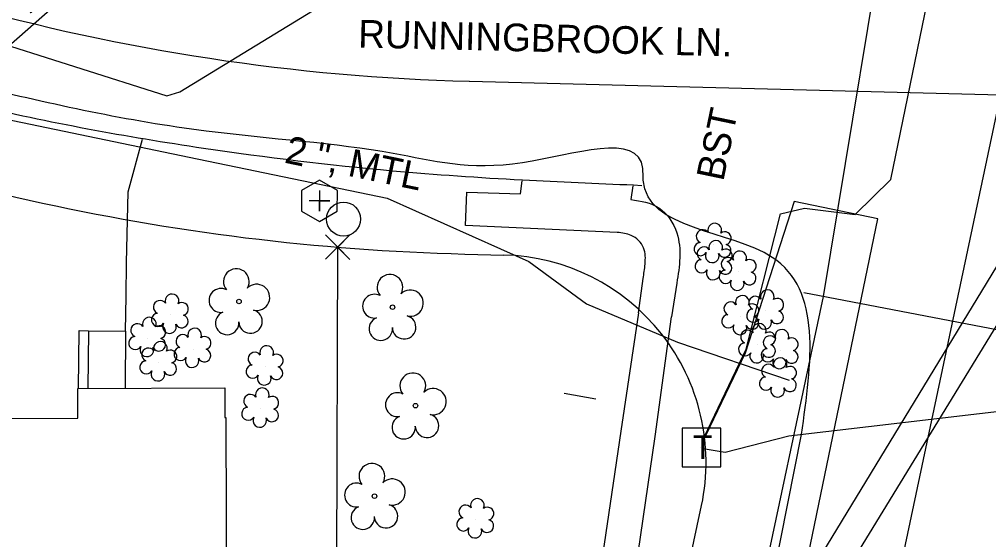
# Model space of a CAD drawing. Extents: x 1614427 to 1617186, y 896524 to 905462.
# Drawn here: x 1616487.6 to 1616627.8, y 901599.9 to 901675.1 of the extents above; entities that cross this region are included whole.
import ezdxf

# ---------------------------------------------------------------- set-up
doc = ezdxf.new("R2010")
doc.units = 0
for name, color, linetype in [('Exist Building', 7, 'Continuous'), ('Exist Horizontal Alignment', 7, 'Continuous'), ('Exist Other Culture Area Outline', 7, 'Continuous'), ('Exist Other Culture Sign', 7, 'Continuous'), ('Exist Property Corner CELL', 7, 'Continuous'), ('Exist Property Line', 7, 'Continuous'), ('Exist Right of Way Line', 7, 'Continuous'), ('Exist Roads Curbs', 7, 'Continuous'), ('Exist Roads EOP', 7, 'Continuous'), ('Exist Roads EOP Other', 7, 'Continuous'), ('Exist Roads EOP Text', 7, 'Continuous'), ('Exist Structure Minor Pipes RCP 18 Inch', 7, 'Continuous'), ('Exist Structure Minor Pipes RCP 18 Inch Text', 7, 'Continuous'), ('Exist Utilities Gas UG Line SUE LOS B', 7, 'Continuous'), ('Exist Utilities Gas UG Line SUE LOS B Text', 7, 'Continuous'), ('Exist Utilities Other Pole CELL', 7, 'Continuous'), ('Exist Utilities Sanitary Sewer Clean-Out CELL', 7, 'Continuous'), ('Exist Utilities Telephone Pedestal CELL', 7, 'Continuous'), ('Exist Utilities Telephone UG Cable SUE LOS B', 7, 'Continuous'), ('Exist Utilities Telephone UG FO SUE LOS D', 7, 'Continuous'), ('Exist Utilities TV UG FO Cable SUE LOS D', 7, 'Continuous'), ('Exist Utilities Water UG Line SUE LOS B', 7, 'Continuous'), ('Exist Vegetation Shrub CELL', 7, 'Continuous'), ('Exist Vegetation Tree CELL', 7, 'Continuous')]:
    doc.layers.add(name, color=color, linetype=linetype)

# ---------------------------------------------------------------- blocks, each defined once
blk = doc.blocks.new('EXIST UTILITIES SANITARY SEWER CLEAN-OUT')
at = {"layer": 'Exist Utilities Sanitary Sewer Clean-Out CELL'}
blk.add_line((0, 0), (0, 0), dxfattribs=at)
blk.add_lwpolyline([(-0.0516, 0.0299), (-0.0517, -0.0297), (-0.0001, -0.0596), (0.0516, -0.0299), (0.0517, 0.0297), (0.0001, 0.0596)], close=True, dxfattribs=at)
blk.add_lwpolyline([(0, 0.0302), (0, -0.0302), (0, 0), (0.0302, 0), (-0.0302, 0)], dxfattribs=at)
blk = doc.blocks.new('EXIST UTILITIES TELEPHONE PEDESTAL')
at = {"layer": 'Exist Utilities Telephone Pedestal CELL'}
blk.add_line((0, 0), (0, 0), dxfattribs=at)
blk.add_lwpolyline([(-0.0545, -0.0565), (0.0574, -0.0565), (0.0574, 0.0554), (-0.0545, 0.0554), (-0.0545, -0.0565)], dxfattribs=at)
blk.add_text('T', height=0.0684, dxfattribs=at).set_placement((-0.0226, -0.0343))

msp = doc.modelspace()

# ---------------------------------------------------------------- linework, layer by layer
at = {"layer": 'Exist Building'}
msp.add_lwpolyline([(1616517.46, 901617.54), (1616517.6, 901573.7), (1616484.75, 901573.6), (1616484.61, 901617.4), (1616496.06, 901617.43), (1616496.05, 901621.76), (1616517.31, 901621.83), (1616517.32, 901617.54)], close=True, dxfattribs=at)
at = {"layer": 'Exist Horizontal Alignment'}
for p, q in [((1616574.86, 901406.65), (1616630.66, 901669.55)), ((1616552.68, 901666.19), (1616629.52, 901664.2))]:
    msp.add_line(p, q, dxfattribs=at)
msp.add_arc((1616560.48, 901967.64), 301.56, 239.9333, 268.5167, dxfattribs=at)
at = {"layer": 'Exist Other Culture Area Outline'}
for points in [[(1616497.6, 901630.1), (1616497.52, 901621.76)], [(1616502.97, 901630.02), (1616502.92, 901621.78)]]:
    msp.add_lwpolyline(points, dxfattribs=at)
at = {"layer": 'Exist Other Culture Sign'}
msp.add_line((1616570.96, 901620.2), (1616566.37, 901621.04), dxfattribs=at)
at = {"layer": 'Exist Property Corner CELL'}
msp.add_line((1616533.65, 901642.19), (1616533.65, 901642.19), dxfattribs=at)
msp.add_lwpolyline([(1616531.88, 901643.96), (1616535.41, 901640.42), (1616533.65, 901642.19), (1616535.42, 901643.95), (1616531.87, 901640.43)], dxfattribs=at)
at = {"layer": 'Exist Property Line'}
msp.add_line((1616533.26, 901496.44), (1616533.65, 901642.19), dxfattribs=at)
at = {"layer": 'Exist Right of Way Line'}
for p, q in [((1616552.03, 901641.19), (1616557.69, 901641.05)), ((1616545.51, 901412.88), (1616586.26, 901604.83))]:
    msp.add_line(p, q, dxfattribs=at)
for centre, radius, start, end in [((1616560.48, 901967.64), 326.56, 246.2087, 268.5167), ((1616556.91, 901611.06), 30, 348.0167, 88.5167)]:
    msp.add_arc(centre, radius, start, end, dxfattribs=at)
at = {"layer": 'Exist Roads Curbs'}
msp.add_line((1616577.63, 901651.07), (1616576.44, 901651.14), dxfattribs=at)
msp.add_spline([(1616576.44, 901651.14), (1616560.36, 901651.87), (1616541.57, 901653.2), (1616514.26, 901656.47), (1616480.87, 901662.8), (1616452.55, 901670.88), (1616427.97, 901679.5)], degree=3, dxfattribs=at)
at = {"layer": 'Exist Roads EOP'}
msp.add_lwpolyline([(1616540.19, 901329.11), (1616548.81, 901369.07), (1616557.77, 901410.37), (1616567.02, 901453.27), (1616575.93, 901495.52), (1616585.07, 901537.99), (1616593.68, 901579.55), (1616600.7, 901615.07)], dxfattribs=at)
msp.add_spline([(1616600.7, 901615.07), (1616596.49, 901640.71), (1616577.82, 901651.88), (1616577.76, 901653.58), (1616560.38, 901654.4), (1616541.66, 901655.74), (1616514.62, 901658.97), (1616481.57, 901665.46), (1616453.29, 901673.28), (1616429.01, 901681.85), (1616427.56, 901682.36), (1616413.54, 901687.44), (1616400.43, 901690.54), (1616382.85, 901691.64), (1616359.81, 901688.16), (1616349.76, 901685.26), (1616334.54, 901681.3), (1616320.23, 901678.77)], degree=3, dxfattribs=at)
at = {"layer": 'Exist Roads EOP Other'}
for p, q in [((1616576.34, 901651.06), (1616576.04, 901649.07)), ((1616577.14, 901632.7), (1616577.81, 901637.66)), ((1616582.68, 901636.98), (1616581.89, 901632.1))]:
    msp.add_line(p, q, dxfattribs=at)
for points in [[(1616496.17, 901621.76), (1616496.29, 901630.12), (1616497.6, 901630.1), (1616502.97, 901630.02), (1616503.05, 901635.11), (1616503.13, 901639.91), (1616503.35, 901650.21), (1616505.44, 901657.82)], [(1616574.07, 901644.32), (1616552.13, 901645.33), (1616552.32, 901650.15), (1616560.09, 901649.9), (1616560.34, 901651.77)], [(1616577.14, 901632.7), (1616574.57, 901615.55), (1616571.08, 901591.72), (1616567.64, 901567.68), (1616564.77, 901548.32), (1616561.36, 901524.77), (1616566.36, 901524.04), (1616569.77, 901547.58), (1616572.64, 901566.94), (1616576.08, 901590.99), (1616579.57, 901614.81), (1616581.89, 901632.1)]]:
    msp.add_lwpolyline(points, dxfattribs=at)
for points in [[(1616576.04, 901649.07), (1616580.09, 901647.88), (1616582.68, 901644.24), (1616582.68, 901636.98)], [(1616577.81, 901637.66), (1616578.09, 901639.73), (1616577.86, 901642.1), (1616576.1, 901643.89), (1616574.07, 901644.32)]]:
    msp.add_spline(points, degree=3, dxfattribs=at)
at = {"layer": 'Exist Structure Minor Pipes RCP 18 Inch'}
msp.add_line((1616479.56, 901665.56), (1616500.34, 901683.9), dxfattribs=at)
msp.add_line((1616479.56, 901665.56), (1616500.34, 901683.9), dxfattribs=at)
at = {"layer": 'Exist Utilities Gas UG Line SUE LOS B'}
for points in [[(1616538.79, 901324.29), (1616552.84, 901386.17), (1616571.68, 901471.14), (1616584.04, 901531.54), (1616593.62, 901586.74), (1616603.9, 901635.05), (1616614.54, 901699.5), (1616631.36, 901792.12), (1616640.8, 901853.71), (1616647.39, 901906.62), (1616655.55, 901983.89), (1616661.01, 902037.25)], [(1616326.48, 901676.74), (1616348.68, 901680.41), (1616373.14, 901686.79), (1616383.03, 901688.18), (1616402.08, 901686.65), (1616424, 901679.78), (1616450.55, 901670.16), (1616479.45, 901662), (1616512.17, 901655.22), (1616540.79, 901649.29), (1616561.3, 901640.13), (1616569.63, 901633.99), (1616582.76, 901628.46), (1616598.92, 901622.96)], [(1616917.65, 901571.58), (1616880.41, 901608.23), (1616849.92, 901623.71), (1616822.5, 901631.75), (1616770.94, 901633.74), (1616722.82, 901632.98), (1616657.05, 901629.46), (1616645.52, 901627.05), (1616601.03, 901635.6)]]:
    msp.add_lwpolyline(points, dxfattribs=at)
at = {"layer": 'Exist Utilities Other Pole CELL'}
msp.add_circle((1616534.49, 901646.25), 2.46, dxfattribs=at)
at = {"layer": 'Exist Utilities Telephone UG Cable SUE LOS B'}
for points in [[(1616586.65, 901614.7), (1616592.7, 901627.45), (1616597.67, 901647), (1616601.16, 901647.82), (1616608.45, 901646.9), (1616613.6, 901651.99), (1616633.98, 901750.98), (1616649.47, 901834.39), (1616660.58, 901920.16), (1616668.64, 902000.09), (1616671.96, 902044.94), (1616671.51, 902046.39), (1616670.53, 902047.17), (1616656.18, 902049.88), (1616655.65, 902049.04), (1616655.13, 902049.4), (1616655.43, 902048.87), (1616655.12, 902049.21)], [(1616676.95, 901705.21), (1616672.98, 901671.34), (1616668.82, 901642.52), (1616664.25, 901627.28), (1616637.98, 901619.42), (1616598.88, 901614.85), (1616589.68, 901612.48), (1616586.51, 901613.01)], [(1616540.9, 901309.07), (1616550.09, 901354.34), (1616575.63, 901474.61), (1616594.08, 901560.69), (1616611.75, 901646.29), (1616599.65, 901648.79), (1616592.58, 901626.87), (1616586.28, 901613.8)]]:
    msp.add_lwpolyline(points, dxfattribs=at)
at = {"layer": 'Exist Utilities Telephone UG FO SUE LOS D'}
msp.add_lwpolyline([(1616540.12, 901401.87), (1616570.93, 901543.95), (1616667.35, 901702.61)], dxfattribs=at)
at = {"layer": 'Exist Utilities TV UG FO Cable SUE LOS D'}
msp.add_lwpolyline([(1616152.19, 899610.51), (1616181.4, 899742.23), (1616224.51, 899936.62), (1616270.68, 900144.79), (1616313.06, 900339.79), (1616354.51, 900530.51), (1616387.28, 900682.32), (1616420.05, 900834.14), (1616462.24, 901026.32), (1616489.27, 901166.41), (1616544.61, 901400.99), (1616575.34, 901543.24), (1616671.95, 901701.27)], dxfattribs=at)
at = {"layer": 'Exist Utilities Water UG Line SUE LOS B'}
msp.add_lwpolyline([(1616377.76, 901712.49), (1616386.98, 901706.49), (1616408.27, 901697.32), (1616425.93, 901691.58), (1616468.83, 901676.83), (1616508.94, 901664.1), (1616510.82, 901664.64), (1616537.41, 901680.97), (1616540.7, 901682.62)], dxfattribs=at)
at = {"layer": 'Exist Vegetation Shrub CELL'}
for p, q in [((1616587.93, 901642.61), (1616587.93, 901642.61)), ((1616588.07, 901640.12), (1616588.07, 901640.12)), ((1616591.55, 901638.6), (1616591.55, 901638.6)), ((1616509.46, 901632.38), (1616509.46, 901632.38)), ((1616595.53, 901632.98), (1616595.53, 901632.98)), ((1616591.94, 901632.17), (1616591.94, 901632.17)), ((1616506.18, 901629.02), (1616506.18, 901629.02)), ((1616512.73, 901627.45), (1616512.73, 901627.45)), ((1616594.36, 901628.11), (1616594.36, 901628.11)), ((1616597.64, 901627.26), (1616597.64, 901627.26)), ((1616507.78, 901625.51), (1616507.78, 901625.51)), ((1616523.15, 901624.9), (1616523.15, 901624.9)), ((1616597.38, 901623.15), (1616597.38, 901623.15)), ((1616522.51, 901618.8), (1616522.51, 901618.8)), ((1616553.62, 901602.79), (1616553.62, 901602.79))]:
    msp.add_line(p, q, dxfattribs=at)
for centre, radius, start, end in [((1616588.16, 901644.65), 0.99, 334.8391, 200.4717), ((1616586.45, 901643.74), 0.968, 35.8908, 245.4216), ((1616589.6, 901643.48), 0.929, 284.4567, 126.0861), ((1616586.13, 901641.91), 0.955, 95.1099, 327.9534), ((1616586.59, 901641.25), 0.968, 35.8908, 245.4216), ((1616588.3, 901642.16), 0.99, 334.8391, 200.4717), ((1616589.57, 901641.68), 0.937, 204.9913, 73.4601), ((1616587.8, 901640.93), 0.984, 151.2797, 21.387), ((1616589.74, 901640.99), 0.929, 284.4567, 126.0861), ((1616591.78, 901640.64), 0.99, 334.8391, 200.4717), ((1616586.27, 901639.42), 0.955, 95.1099, 327.9534), ((1616589.7, 901639.2), 0.937, 204.9913, 73.4601), ((1616590.07, 901639.73), 0.968, 35.8908, 245.4216), ((1616593.22, 901639.47), 0.929, 284.4567, 126.0861), ((1616587.94, 901638.44), 0.984, 151.2797, 21.387), ((1616589.75, 901637.89), 0.955, 95.1099, 327.9534), ((1616593.19, 901637.67), 0.937, 204.9913, 73.4601), ((1616591.42, 901636.92), 0.984, 151.2797, 21.387), ((1616509.69, 901634.42), 0.99, 334.8391, 200.4717), ((1616592.17, 901634.21), 0.99, 334.8391, 200.4717), ((1616595.76, 901635.02), 0.99, 334.8391, 200.4717), ((1616507.97, 901633.51), 0.968, 35.8908, 245.4216), ((1616511.13, 901633.25), 0.929, 284.4567, 126.0861), ((1616590.45, 901633.3), 0.968, 35.8908, 245.4216), ((1616593.61, 901633.04), 0.929, 284.4567, 126.0861), ((1616594.05, 901634.11), 0.968, 35.8908, 245.4216), ((1616597.2, 901633.85), 0.929, 284.4567, 126.0861), ((1616507.66, 901631.68), 0.955, 95.1099, 327.9534), ((1616511.09, 901631.46), 0.937, 204.9913, 73.4601), ((1616590.14, 901631.47), 0.955, 95.1099, 327.9534), ((1616593.73, 901632.28), 0.955, 95.1099, 327.9534), ((1616597.17, 901632.05), 0.937, 204.9913, 73.4601), ((1616504.7, 901630.15), 0.968, 35.8908, 245.4216), ((1616506.41, 901631.06), 0.99, 334.8391, 200.4717), ((1616509.33, 901630.7), 0.984, 151.2797, 21.387), ((1616591.81, 901630.49), 0.984, 151.2797, 21.387), ((1616593.57, 901631.24), 0.937, 204.9913, 73.4601), ((1616594.59, 901630.15), 0.99, 334.8391, 200.4717), ((1616595.4, 901631.3), 0.984, 151.2797, 21.387), ((1616507.85, 901629.89), 0.929, 284.4567, 126.0861), ((1616511.24, 901628.57), 0.968, 35.8908, 245.4216), ((1616512.96, 901629.49), 0.99, 334.8391, 200.4717), ((1616592.88, 901629.23), 0.968, 35.8908, 245.4216), ((1616596.03, 901628.98), 0.929, 284.4567, 126.0861), ((1616597.87, 901629.3), 0.99, 334.8391, 200.4717), ((1616504.38, 901628.32), 0.955, 95.1099, 327.9534), ((1616507.82, 901628.09), 0.937, 204.9913, 73.4601), ((1616508.01, 901627.55), 0.99, 334.8391, 200.4717), ((1616514.4, 901628.32), 0.929, 284.4567, 126.0861), ((1616592.56, 901627.4), 0.955, 95.1099, 327.9534), ((1616596.15, 901628.39), 0.968, 35.8908, 245.4216), ((1616599.31, 901628.13), 0.929, 284.4567, 126.0861), ((1616506.05, 901627.34), 0.984, 151.2797, 21.387), ((1616506.29, 901626.63), 0.968, 35.8908, 245.4216), ((1616509.45, 901626.37), 0.929, 284.4567, 126.0861), ((1616510.93, 901626.74), 0.955, 95.1099, 327.9534), ((1616514.36, 901626.52), 0.937, 204.9913, 73.4601), ((1616521.66, 901626.02), 0.968, 35.8908, 245.4216), ((1616523.38, 901626.94), 0.99, 334.8391, 200.4717), ((1616594.23, 901626.42), 0.984, 151.2797, 21.387), ((1616595.84, 901626.55), 0.955, 95.1099, 327.9534), ((1616596, 901627.18), 0.937, 204.9913, 73.4601), ((1616599.27, 901626.33), 0.937, 204.9913, 73.4601), ((1616505.98, 901624.8), 0.955, 95.1099, 327.9534), ((1616509.41, 901624.58), 0.937, 204.9913, 73.4601), ((1616512.6, 901625.76), 0.984, 151.2797, 21.387), ((1616524.82, 901625.77), 0.929, 284.4567, 126.0861), ((1616597.51, 901625.57), 0.984, 151.2797, 21.387), ((1616597.61, 901625.19), 0.99, 334.8391, 200.4717), ((1616507.65, 901623.82), 0.984, 151.2797, 21.387), ((1616521.35, 901624.19), 0.955, 95.1099, 327.9534), ((1616524.78, 901623.97), 0.937, 204.9913, 73.4601), ((1616595.9, 901624.28), 0.968, 35.8908, 245.4216), ((1616599.05, 901624.02), 0.929, 284.4567, 126.0861), ((1616523.02, 901623.21), 0.984, 151.2797, 21.387), ((1616595.58, 901622.45), 0.955, 95.1099, 327.9534), ((1616599.02, 901622.22), 0.937, 204.9913, 73.4601), ((1616522.74, 901620.84), 0.99, 334.8391, 200.4717), ((1616597.25, 901621.47), 0.984, 151.2797, 21.387), ((1616521.03, 901619.93), 0.968, 35.8908, 245.4216), ((1616524.18, 901619.67), 0.929, 284.4567, 126.0861), ((1616520.71, 901618.1), 0.955, 95.1099, 327.9534), ((1616524.15, 901617.87), 0.937, 204.9913, 73.4601), ((1616522.38, 901617.12), 0.984, 151.2797, 21.387), ((1616553.85, 901604.83), 0.99, 334.8391, 200.4717), ((1616552.14, 901603.91), 0.968, 35.8908, 245.4216), ((1616555.29, 901603.65), 0.929, 284.4567, 126.0861), ((1616551.82, 901602.08), 0.955, 95.1099, 327.9534), ((1616553.49, 901601.1), 0.984, 151.2797, 21.387), ((1616555.26, 901601.86), 0.937, 204.9913, 73.4601)]:
    msp.add_arc(centre, radius, start, end, dxfattribs=at)
at = {"layer": 'Exist Vegetation Tree CELL'}
for p, q in [((1616519.37, 901634.33), (1616519.37, 901634.33)), ((1616541.58, 901633.5), (1616541.58, 901633.5)), ((1616544.9, 901619.25), (1616544.9, 901619.25)), ((1616538.97, 901606.17), (1616538.97, 901606.17))]:
    msp.add_line(p, q, dxfattribs=at)
for centre in [(1616519.37, 901634.33), (1616541.58, 901633.5), (1616544.9, 901619.25), (1616538.97, 901606.17)]:
    msp.add_circle(centre, 0.326, dxfattribs=at)
for centre, radius, start, end in [((1616518.99, 901637.2), 1.86, 330.1651, 219.7134), ((1616541.2, 901636.37), 1.86, 330.1651, 219.7134), ((1616521.92, 901634.92), 1.9, 257.1011, 134.1999), ((1616516.77, 901634.48), 1.73, 62.6636, 279.3457), ((1616538.98, 901633.65), 1.73, 62.6636, 279.3457), ((1616544.13, 901634.09), 1.9, 257.1011, 134.1999), ((1616517.67, 901631.21), 1.69, 111.5671, 6.231), ((1616521.04, 901631.43), 1.7, 181.2822, 74.56), ((1616539.88, 901630.38), 1.69, 111.5671, 6.231), ((1616543.25, 901630.6), 1.7, 181.2822, 74.56), ((1616544.51, 901622.12), 1.86, 330.1651, 219.7134), ((1616542.29, 901619.4), 1.73, 62.6636, 279.3457), ((1616547.45, 901619.84), 1.9, 257.1011, 134.1999), ((1616543.19, 901616.13), 1.69, 111.5671, 6.231), ((1616546.57, 901616.35), 1.7, 181.2822, 74.56), ((1616538.59, 901609.04), 1.86, 330.1651, 219.7134), ((1616541.52, 901606.76), 1.9, 257.1011, 134.1999), ((1616536.37, 901606.33), 1.73, 62.6636, 279.3457), ((1616537.27, 901603.05), 1.69, 111.5671, 6.231), ((1616540.64, 901603.27), 1.7, 181.2822, 74.56)]:
    msp.add_arc(centre, radius, start, end, dxfattribs=at)

# ---------------------------------------------------------------- block references
at = {"layer": 'Exist Utilities Sanitary Sewer Clean-Out CELL', "xscale": 50, "yscale": 50}
msp.add_blockref('EXIST UTILITIES SANITARY SEWER CLEAN-OUT', (1616531.01, 901648.89), dxfattribs=at)
at = {"layer": 'Exist Utilities Telephone Pedestal CELL', "xscale": 50, "yscale": 50}
msp.add_blockref('EXIST UTILITIES TELEPHONE PEDESTAL', (1616586.16, 901613.24), dxfattribs=at)

# ---------------------------------------------------------------- texts
at = {"layer": 'Exist Roads EOP Text'}
for s, rotation, p in [('RUNNINGBROOK LN.', 358.628, (1616536.58, 901671.08)), ('BST', 78.2247, (1616589.39, 901651.6))]:
    msp.add_text(s, height=4, rotation=rotation, dxfattribs=at).set_placement(p)
at = {"layer": 'Exist Structure Minor Pipes RCP 18 Inch Text'}
msp.add_text('18" RCP', height=4, rotation=41.4259, dxfattribs=at).set_placement((1616481.94, 901669.52))
at = {"layer": 'Exist Utilities Gas UG Line SUE LOS B Text'}
msp.add_text('2 ", MTL', height=4, rotation=348.2918, dxfattribs=at).set_placement((1616525.82, 901654.43))

doc.saveas('drawing.dxf')
